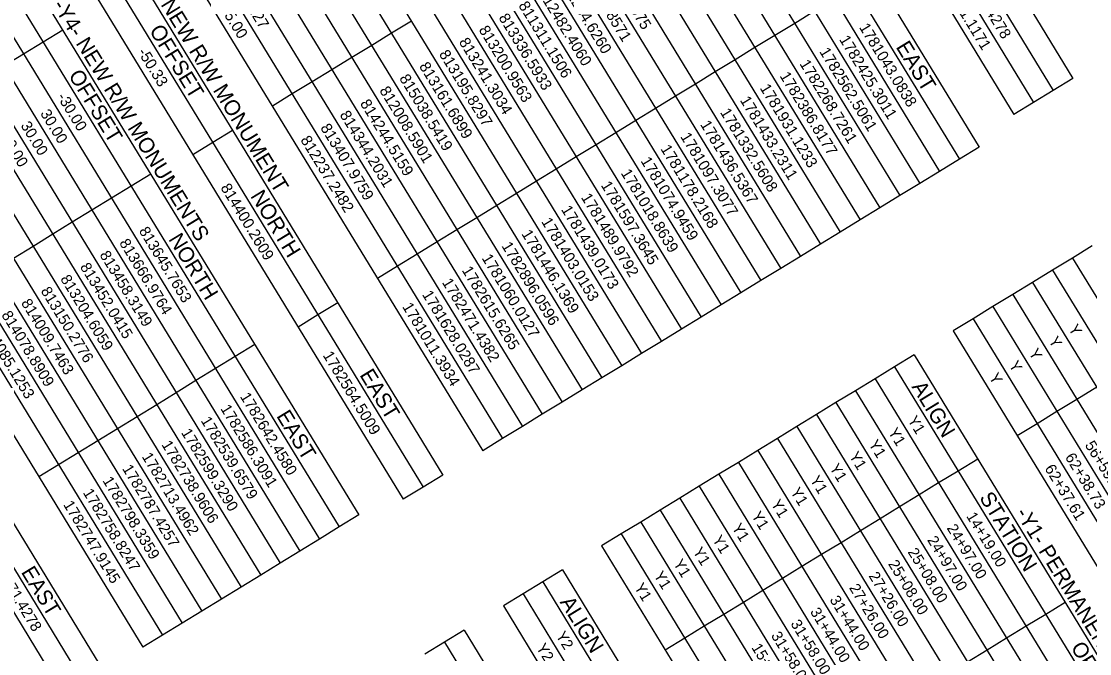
# Model space of a CAD drawing. Extents: x 1753086 to 1770987, y 792577 to 812636.
# Drawn here: x 1760334 to 1764623, y 802249 to 804785 of the extents above; entities that cross this region are included whole.
import ezdxf

# ---------------------------------------------------------------- set-up
doc = ezdxf.new("R2010")
doc.units = 0
for name, color, linetype in [('CTL Sheet Notes CELL', 7, 'Continuous'), ('CTL Sheet Table Cell', 7, 'Continuous'), ('CTL Sheet Text', 7, 'Continuous')]:
    doc.layers.add(name, color=color, linetype=linetype)

msp = doc.modelspace()

# ---------------------------------------------------------------- linework, layer by layer
at = {"layer": 'CTL Sheet Table Cell'}
for p, q in [((1762756.9, 807499.7), (1764555.5, 804556.1)), ((1762678.1, 807451.5), (1764476.6, 804507.9)), ((1762599.2, 807403.3), (1764397.8, 804459.7)), ((1762520.4, 807355.2), (1764318.9, 804411.5)), ((1762360.9, 807257.7), (1764179.9, 804280.6)), ((1762281.2, 807209), (1764100.2, 804231.9)), ((1762201.4, 807160.3), (1764020.4, 804183.2)), ((1762121.7, 807111.5), (1763940.7, 804134.5)), ((1762041.9, 807062.8), (1763860.9, 804085.7)), ((1761962.2, 807014.1), (1763781.2, 804037)), ((1761882.4, 806965.4), (1763701.4, 803988.3)), ((1761802.7, 806916.7), (1763621.7, 803939.6)), ((1761723, 806867.9), (1763542, 803890.9)), ((1761643.2, 806819.2), (1763462.2, 803842.1)), ((1761563.5, 806770.5), (1763382.5, 803793.4)), ((1761483.7, 806721.8), (1763302.7, 803744.7)), ((1761404, 806673), (1763223, 803696)), ((1761324.2, 806624.3), (1763143.2, 803647.2)), ((1761244.5, 806575.6), (1763063.5, 803598.5)), ((1761164.8, 806526.9), (1762983.7, 803549.8)), ((1761085, 806478.1), (1762904, 803501.1)), ((1761005.3, 806429.4), (1762824.3, 803452.3)), ((1760925.5, 806380.7), (1762744.5, 803403.6)), ((1760845.8, 806332), (1762664.8, 803354.9)), ((1760766, 806283.3), (1762585, 803306.2)), ((1760686.3, 806234.5), (1762505.3, 803257.5)), ((1760606.6, 806185.8), (1762425.5, 803208.7)), ((1760526.8, 806137.1), (1762345.8, 803160)), ((1760447.1, 806088.4), (1762266.1, 803111.3)), ((1760367.3, 806039.6), (1762186.3, 803062.6)), ((1760207.8, 805942.2), (1762026.8, 802965.1)), ((1760128.1, 805893.5), (1761947.1, 802916.4)), ((1760048.4, 805844.7), (1761867.3, 802867.7)), ((1759890.7, 805748.4), (1761689.2, 802804.8)), ((1759811.8, 805700.2), (1761610.4, 802756.6)), ((1759733, 805652), (1761531.5, 802708.4)), ((1759654.1, 805603.9), (1761452.7, 802660.2)), ((1759575.3, 805555.7), (1761373.8, 802612.1)), ((1759496.4, 805507.5), (1761295, 802563.9)), ((1759417.6, 805459.3), (1761216.1, 802515.7)), ((1759338.7, 805411.2), (1761137.3, 802467.5)), ((1759259.9, 805363), (1761058.4, 802419.4)), ((1759181, 805314.8), (1760979.6, 802371.2)), ((1759102.2, 805266.6), (1760900.7, 802323)), ((1759023.3, 805218.5), (1760821.9, 802274.8)), ((1758865.6, 805122.1), (1760664.2, 802178.5)), ((1758786.8, 805073.9), (1760585.4, 802130.3)), ((1758707.9, 805025.8), (1760506.5, 802082.1)), ((1763518.4, 804825.6), (1763438.7, 804776.9)), ((1761900, 804785.8), (1761820.2, 804737.1)), ((1763438.7, 804776.9), (1763358.9, 804728.1)), ((1760500.9, 804749.7), (1760422, 804701.5)), ((1761820.2, 804737.1), (1761740.5, 804688.4)), ((1763358.9, 804728.1), (1763279.2, 804679.4)), ((1760422, 804701.5), (1760343.2, 804653.3)), ((1761740.5, 804688.4), (1761660.8, 804639.7)), ((1763279.2, 804679.4), (1763199.4, 804630.7)), ((1760343.2, 804653.3), (1760264.3, 804605.1)), ((1761660.8, 804639.7), (1761581, 804590.9)), ((1761581, 804590.9), (1761501.3, 804542.2)), ((1763199.4, 804630.7), (1763119.7, 804582)), ((1763119.7, 804582), (1763039.9, 804533.2)), ((1764555.5, 804556.1), (1764476.6, 804507.9)), ((1761501.3, 804542.2), (1761421.5, 804493.5)), ((1763039.9, 804533.2), (1762960.2, 804484.5)), ((1764476.6, 804507.9), (1764397.8, 804459.7)), ((1761421.5, 804493.5), (1761341.8, 804444.8)), ((1762960.2, 804484.5), (1762880.5, 804435.8)), ((1762880.5, 804435.8), (1762800.7, 804387.1)), ((1764397.8, 804459.7), (1764318.9, 804411.5)), ((1762800.7, 804387.1), (1762721, 804338.3)), ((1761182.3, 804347.3), (1761102.6, 804298.6)), ((1762721, 804338.3), (1762641.2, 804289.6)), ((1761102.6, 804298.6), (1761022.8, 804249.9)), ((1762641.2, 804289.6), (1762561.5, 804240.9)), ((1764179.9, 804280.6), (1764100.2, 804231.9)), ((1762561.5, 804240.9), (1762481.7, 804192.2)), ((1764100.2, 804231.9), (1764020.4, 804183.2)), ((1760854.2, 804171.5), (1760775.3, 804123.3)), ((1762481.7, 804192.2), (1762402, 804143.5)), ((1764020.4, 804183.2), (1763940.7, 804134.5)), ((1760775.3, 804123.3), (1760696.5, 804075.1)), ((1762402, 804143.5), (1762322.3, 804094.7)), ((1763940.7, 804134.5), (1763860.9, 804085.7)), ((1760696.5, 804075.1), (1760617.6, 804026.9)), ((1762322.3, 804094.7), (1762242.5, 804046)), ((1763860.9, 804085.7), (1763781.2, 804037)), ((1762242.5, 804046), (1762162.8, 803997.3)), ((1763781.2, 804037), (1763701.4, 803988.3)), ((1760617.6, 804026.9), (1760538.8, 803978.7)), ((1762162.8, 803997.3), (1762083, 803948.6)), ((1760538.8, 803978.7), (1760459.9, 803930.6)), ((1762083, 803948.6), (1762003.3, 803899.8)), ((1763701.4, 803988.3), (1763621.7, 803939.6)), ((1760459.9, 803930.6), (1760381.1, 803882.4)), ((1763621.7, 803939.6), (1763542, 803890.9)), ((1760381.1, 803882.4), (1760302.2, 803834.2)), ((1762003.3, 803899.8), (1761923.5, 803851.1)), ((1763542, 803890.9), (1763462.2, 803842.1)), ((1764633.6, 803884.2), (1764553.8, 803835.4)), ((1761923.5, 803851.1), (1761843.8, 803802.4)), ((1763462.2, 803842.1), (1763382.5, 803793.4)), ((1764553.8, 803835.4), (1764473.9, 803786.7)), ((1764553.8, 803835.4), (1766354.2, 800888.7)), ((1761843.8, 803802.4), (1761764.1, 803753.7)), ((1763382.5, 803793.4), (1763302.7, 803744.7)), ((1764473.9, 803786.7), (1764394.1, 803737.9)), ((1764473.9, 803786.7), (1766274.4, 800840)), ((1763302.7, 803744.7), (1763223, 803696)), ((1764394.1, 803737.9), (1764314.3, 803689.1)), ((1764394.1, 803737.9), (1766194.6, 800791.2)), ((1763223, 803696), (1763143.2, 803647.2)), ((1764314.3, 803689.1), (1764234.5, 803640.4)), ((1764314.3, 803689.1), (1766114.7, 800742.4)), ((1761604.6, 803656.2), (1761524.8, 803607.5)), ((1763143.2, 803647.2), (1763063.5, 803598.5)), ((1761524.8, 803607.5), (1761445.1, 803558.8)), ((1764234.5, 803640.4), (1764154.7, 803591.6)), ((1764234.5, 803640.4), (1766034.9, 800693.7)), ((1763063.5, 803598.5), (1762983.7, 803549.8)), ((1764154.7, 803591.6), (1764074.9, 803542.8)), ((1764154.7, 803591.6), (1765955.1, 800644.9)), ((1762983.7, 803549.8), (1762904, 803501.1)), ((1764074.9, 803542.8), (1765875.3, 800596.1)), ((1761271.7, 803488.1), (1761192.8, 803439.9)), ((1762904, 803501.1), (1762824.3, 803452.3)), ((1761192.8, 803439.9), (1761114, 803391.8)), ((1762824.3, 803452.3), (1762744.5, 803403.6)), ((1763918.1, 803447), (1763839.7, 803399.1)), ((1763918.1, 803447), (1765706.4, 800520.1)), ((1761114, 803391.8), (1761035.1, 803343.6)), ((1762744.5, 803403.6), (1762664.8, 803354.9)), ((1763839.7, 803399.1), (1763761.3, 803351.2)), ((1763839.7, 803399.1), (1765628, 800472.2)), ((1762664.8, 803354.9), (1762585, 803306.2)), ((1763761.3, 803351.2), (1763682.9, 803303.3)), ((1763761.3, 803351.2), (1765549.6, 800424.3)), ((1761035.1, 803343.6), (1760956.3, 803295.4)), ((1762585, 803306.2), (1762505.3, 803257.5)), ((1763682.9, 803303.3), (1763604.5, 803255.4)), ((1763682.9, 803303.3), (1765471.2, 800376.4)), ((1764651.3, 803317), (1764571.5, 803268.2)), ((1760956.3, 803295.4), (1760877.5, 803247.2)), ((1764571.5, 803268.2), (1764491.7, 803219.4)), ((1760877.5, 803247.2), (1760798.6, 803199.1)), ((1762505.3, 803257.5), (1762425.5, 803208.7)), ((1763604.5, 803255.4), (1763526.1, 803207.5)), ((1763604.5, 803255.4), (1765392.8, 800328.5)), ((1764491.7, 803219.4), (1764411.9, 803170.6)), ((1760798.6, 803199.1), (1760719.8, 803150.9)), ((1762425.5, 803208.7), (1762345.8, 803160)), ((1763526.1, 803207.5), (1763447.7, 803159.6)), ((1763526.1, 803207.5), (1765314.4, 800280.6)), ((1760719.8, 803150.9), (1760640.9, 803102.7)), ((1762345.8, 803160), (1762266.1, 803111.3)), ((1763447.7, 803159.6), (1763369.3, 803111.7)), ((1763447.7, 803159.6), (1765236, 800232.7)), ((1764411.9, 803170.6), (1764332.1, 803121.9)), ((1760640.9, 803102.7), (1760562.1, 803054.5)), ((1762266.1, 803111.3), (1762186.3, 803062.6)), ((1763369.3, 803111.7), (1763290.9, 803063.8)), ((1763369.3, 803111.7), (1765157.6, 800184.8)), ((1760562.1, 803054.5), (1760483.2, 803006.4)), ((1763290.9, 803063.8), (1763212.5, 803015.9)), ((1763290.9, 803063.8), (1765079.2, 800136.9)), ((1760483.2, 803006.4), (1760404.4, 802958.2)), ((1763212.5, 803015.9), (1763134.1, 802968)), ((1763212.5, 803015.9), (1765000.8, 800089)), ((1764173.5, 803028.9), (1764095.1, 802981)), ((1762026.8, 802965.1), (1761947.1, 802916.4)), ((1763134.1, 802968), (1763055.7, 802920.1)), ((1763134.1, 802968), (1764922.4, 800041.1)), ((1764095.1, 802981), (1764016.7, 802933.1)), ((1763055.7, 802920.1), (1762977.3, 802872.2)), ((1763055.7, 802920.1), (1764844, 799993.2)), ((1764016.7, 802933.1), (1763938.3, 802885.2)), ((1761947.1, 802916.4), (1761867.3, 802867.7)), ((1763938.3, 802885.2), (1763859.9, 802837.3)), ((1762977.3, 802872.2), (1762898.9, 802824.3)), ((1762977.3, 802872.2), (1764765.6, 799945.3)), ((1763859.9, 802837.3), (1763781.5, 802789.4)), ((1761689.2, 802804.8), (1761610.4, 802756.6)), ((1762898.9, 802824.3), (1762820.5, 802776.4)), ((1762898.9, 802824.3), (1764687.2, 799897.4)), ((1763781.5, 802789.4), (1763703.1, 802741.5)), ((1761610.4, 802756.6), (1761531.5, 802708.4)), ((1762820.5, 802776.4), (1762742.1, 802728.5)), ((1762820.5, 802776.4), (1764608.8, 799849.5)), ((1761531.5, 802708.4), (1761452.7, 802660.2)), ((1762742.1, 802728.5), (1762663.7, 802680.6)), ((1762742.1, 802728.5), (1764530.4, 799801.6)), ((1763703.1, 802741.5), (1763624.7, 802693.6)), ((1761452.7, 802660.2), (1761373.8, 802612.1)), ((1762663.7, 802680.6), (1764452, 799753.7)), ((1763624.7, 802693.6), (1763546.3, 802645.7)), ((1763546.3, 802645.7), (1763467.9, 802597.8)), ((1761373.8, 802612.1), (1761295, 802563.9)), ((1762506, 802584.3), (1762427.1, 802536.1)), ((1762506, 802584.3), (1764304.5, 799640.6)), ((1763467.9, 802597.8), (1763389.5, 802549.9)), ((1761295, 802563.9), (1761216.1, 802515.7)), ((1762427.1, 802536.1), (1762348.3, 802487.9)), ((1762427.1, 802536.1), (1764225.7, 799592.5)), ((1763389.5, 802549.9), (1763311.1, 802502)), ((1761216.1, 802515.7), (1761137.3, 802467.5)), ((1763311.1, 802502), (1763232.7, 802454.1)), ((1761137.3, 802467.5), (1761058.4, 802419.4)), ((1762348.3, 802487.9), (1762269.4, 802439.7)), ((1762348.3, 802487.9), (1764146.8, 799544.3)), ((1763232.7, 802454.1), (1763154.3, 802406.2)), ((1764524.8, 802454), (1764446.4, 802406.1)), ((1761058.4, 802419.4), (1760979.6, 802371.2)), ((1762269.4, 802439.7), (1764068, 799496.1)), ((1763154.3, 802406.2), (1763075.9, 802358.3)), ((1764446.4, 802406.1), (1764368, 802358.2)), ((1760979.6, 802371.2), (1760900.7, 802323)), ((1760900.7, 802323), (1760821.9, 802274.8)), ((1762111.7, 802343.4), (1762032.9, 802295.2)), ((1762111.7, 802343.4), (1763910.3, 799399.7)), ((1763075.9, 802358.3), (1762997.5, 802310.4)), ((1764368, 802358.2), (1764289.6, 802310.3)), ((1762032.9, 802295.2), (1761954, 802247)), ((1762032.9, 802295.2), (1763831.5, 799351.6)), ((1762997.5, 802310.4), (1762919.1, 802262.5)), ((1764289.6, 802310.3), (1764211.2, 802262.4)), ((1764211.2, 802262.4), (1764132.8, 802214.5))]:
    msp.add_line(p, q, dxfattribs=at)

# ---------------------------------------------------------------- texts
at = {"layer": 'CTL Sheet Notes CELL'}
for s, height, p in [('-Y1- NEW R/W MONUMENT', 62.3, (1760797.6, 805006.8)), ('-Y4- NEW R/W MONUMENTS', 61.6, (1760457.9, 804849.6)), ('OFFSET', 62.3, (1760845.9, 804748.6)), ('EAST', 62.3, (1763843.2, 804682.3)), ('OFFSET', 61.6, (1760521.5, 804568.2)), ('NORTH', 62.3, (1761251.8, 804084.2)), ('NORTH', 61.6, (1760922.9, 803911.3)), ('EAST', 62.3, (1761690.2, 803366.8)), ('ALIGN', 61.25, (1763906.5, 803319)), ('EAST', 61.6, (1761356.3, 803201.9)), ('STATION', 61.25, (1764178.2, 802874.4)), ('-Y1- PERMANENT UTILITY EASEMENTS', 61.25, (1764323.6, 802812.6)), ('EAST', 61.6, (1760331.3, 802575.6)), ('ALIGN', 61.6, (1762494.4, 802455.5)), ('OFFSET', 61.25, (1764545.4, 802273.5))]:
    msp.add_text(s, height=height, rotation=301.4249, dxfattribs=at).set_placement(p)
at = {"layer": 'CTL Sheet Text'}
for s, height, p in [('812782.8075', 44.5, (1762647.2, 805043.8)), ('1780671.4278', 44, (1764076.9, 805031.3)), ('812100.8571', 44.5, (1762567.4, 804995)), ('1780701.1171', 44, (1763996.1, 804986.4)), ('812264.6260', 44.5, (1762487.7, 804946.3)), ('155.27', 44.5, (1761198.5, 804905.4)), ('812482.4060', 44.5, (1762408, 804897.6)), ('75.00', 44.5, (1761130.3, 804837.8)), ('811311.1506', 44.5, (1762328.2, 804848.9)), ('813336.5933', 44.5, (1762248.5, 804800.1)), ('813200.9563', 44.5, (1762168.7, 804751.4)), ('1781043.0838', 44.5, (1763695.9, 804761.3)), ('813241.3034', 44.5, (1762089, 804702.7)), ('1782425.3011', 44.5, (1763616.1, 804712.5)), ('1782562.5061', 44.5, (1763536.4, 804663.8)), ('-50.33', 44.5, (1760799.8, 804661.8)), ('813195.8297', 44.5, (1762009.2, 804654)), ('813161.6899', 44.5, (1761929.5, 804605.2)), ('1782268.7261', 44.5, (1763456.7, 804615.1)), ('815038.5419', 44.5, (1761849.8, 804556.5)), ('1782386.8177', 44.5, (1763376.9, 804566.4)), ('812008.5901', 44.5, (1761770, 804507.8)), ('1781931.1233', 44.5, (1763297.2, 804517.7)), ('-30.00', 44, (1760476, 804482.4)), ('814244.5159', 44.5, (1761692.3, 804455.8)), ('1781433.2311', 44.5, (1763217.4, 804468.9)), ('30.00', 44, (1760408.5, 804415.6)), ('814344.2031', 44.5, (1761610.5, 804410.4)), ('1781332.5608', 44.5, (1763137.7, 804420.2)), ('30.00', 44, (1760329.7, 804367.4)), ('813407.9759', 44.5, (1761532.8, 804358.3)), ('1781436.5367', 44.5, (1763057.9, 804371.5)), ('-30.00', 44, (1760239.5, 804337.8)), ('1781097.3077', 44.5, (1762978.2, 804322.8)), ('812237.2482', 44.5, (1761453, 804309.6)), ('1781178.2168', 44.5, (1762898.5, 804274)), ('1781074.9459', 44.5, (1762818.7, 804225.3)), ('1781018.8639', 44.5, (1762739, 804176.6)), ('814400.2609', 44.5, (1761132.1, 804118)), ('1781597.3645', 44.5, (1762659.2, 804127.9)), ('1781489.9792', 44.5, (1762579.5, 804079.1)), ('1781439.0173', 44.5, (1762499.7, 804030.4)), ('1781403.0153', 44.5, (1762420, 803981.7)), ('813645.7653', 44, (1760804.5, 803944.7)), ('1781446.1369', 44.5, (1762340.3, 803933)), ('813666.9764', 44, (1760725.7, 803896.5)), ('813458.3149', 44, (1760646.8, 803848.4)), ('1782896.0596', 44.5, (1762260.5, 803884.3)), ('1781060.0127', 44.5, (1762180.8, 803835.5)), ('813452.0415', 44, (1760568, 803800.2)), ('1782615.6265', 44.5, (1762101, 803786.8)), ('813204.6059', 44, (1760489.1, 803752)), ('1782471.4382', 44.5, (1762021.3, 803738.1)), ('813150.2776', 44, (1760410.3, 803703.8)), ('1781628.0287', 44.5, (1761941.5, 803689.4)), ('814009.7463', 44, (1760331.4, 803655.7)), ('1781011.3934', 44.5, (1761861.8, 803640.6)), ('814078.8909', 44, (1760252.6, 803607.5)), ('814085.1253', 44, (1760173.7, 803559.3)), ('Y', 44.5, (1764536, 803552.6)), ('Y', 44.5, (1764456.2, 803503.9)), ('Y', 44.5, (1764376.4, 803455.1)), ('1782564.5009', 44.5, (1761542.8, 803445.7)), ('Y', 44.5, (1764296.6, 803406.3)), ('Y', 44.5, (1764216.8, 803357.6)), ('1782642.4580', 44, (1761210.6, 803280)), ('1782586.3091', 44, (1761131.8, 803231.8)), ('1782539.6579', 44, (1761052.9, 803183.6)), ('Y1', 43.75, (1763890.7, 803185.6)), ('1782599.3290', 44, (1760974.1, 803135.5)), ('Y1', 43.75, (1763812.3, 803137.7)), ('1782738.9606', 44, (1760895.3, 803087.3)), ('Y1', 43.75, (1763733.9, 803089.8)), ('56+59.42', 44.54, (1764602.1, 803085.7)), ('1782713.4962', 44, (1760816.4, 803039.1)), ('Y1', 43.75, (1763655.5, 803041.9)), ('62+38.73', 44.54, (1764522.3, 803037)), ('1782787.4257', 44, (1760737.6, 802990.9)), ('Y1', 43.75, (1763577.1, 802994)), ('62+37.61', 44.54, (1764440.5, 802991.4)), ('Y1', 43.75, (1763498.7, 802946.1)), ('1782798.3359', 44, (1760658.7, 802942.8)), ('Y1', 43.75, (1763420.3, 802898.2)), ('1782758.8247', 44, (1760579.9, 802894.6)), ('1782747.9145', 44, (1760501, 802846.4)), ('Y1', 43.75, (1763341.9, 802850.3)), ('Y1', 43.75, (1763263.5, 802802.4)), ('14+19.00', 43.75, (1764126.2, 802800.2)), ('Y1', 43.75, (1763185.1, 802754.5)), ('24+97.00', 43.75, (1764047.8, 802752.3)), ('Y1', 43.75, (1763106.7, 802706.6)), ('24+97.00', 43.75, (1763969.4, 802704.4)), ('1780671.4278', 44, (1760185.6, 802653.7)), ('Y1', 43.75, (1763028.3, 802658.7)), ('25+08.00', 43.75, (1763891, 802656.5)), ('Y1', 43.75, (1762949.9, 802610.8)), ('25+08.00', 43.75, (1763812.6, 802608.6)), ('Y1', 43.75, (1762871.5, 802562.9)), ('27+26.00', 43.75, (1763734.2, 802560.7)), ('Y1', 43.75, (1762793.1, 802515)), ('27+26.00', 43.75, (1763655.8, 802512.8)), ('31+44.00', 43.75, (1763577.4, 802464.9)), ('31+44.00', 43.75, (1763499, 802417)), ('31+58.00', 43.75, (1763420.6, 802369)), ('Y2', 44, (1762478.4, 802321.3)), ('31+58.00', 43.75, (1763342.2, 802321.1)), ('Y2', 44, (1762399.6, 802273.1)), ('15+32.00', 43.75, (1763263.8, 802273.2))]:
    msp.add_text(s, height=height, rotation=301.4249, dxfattribs=at).set_placement(p)

doc.saveas('drawing.dxf')
